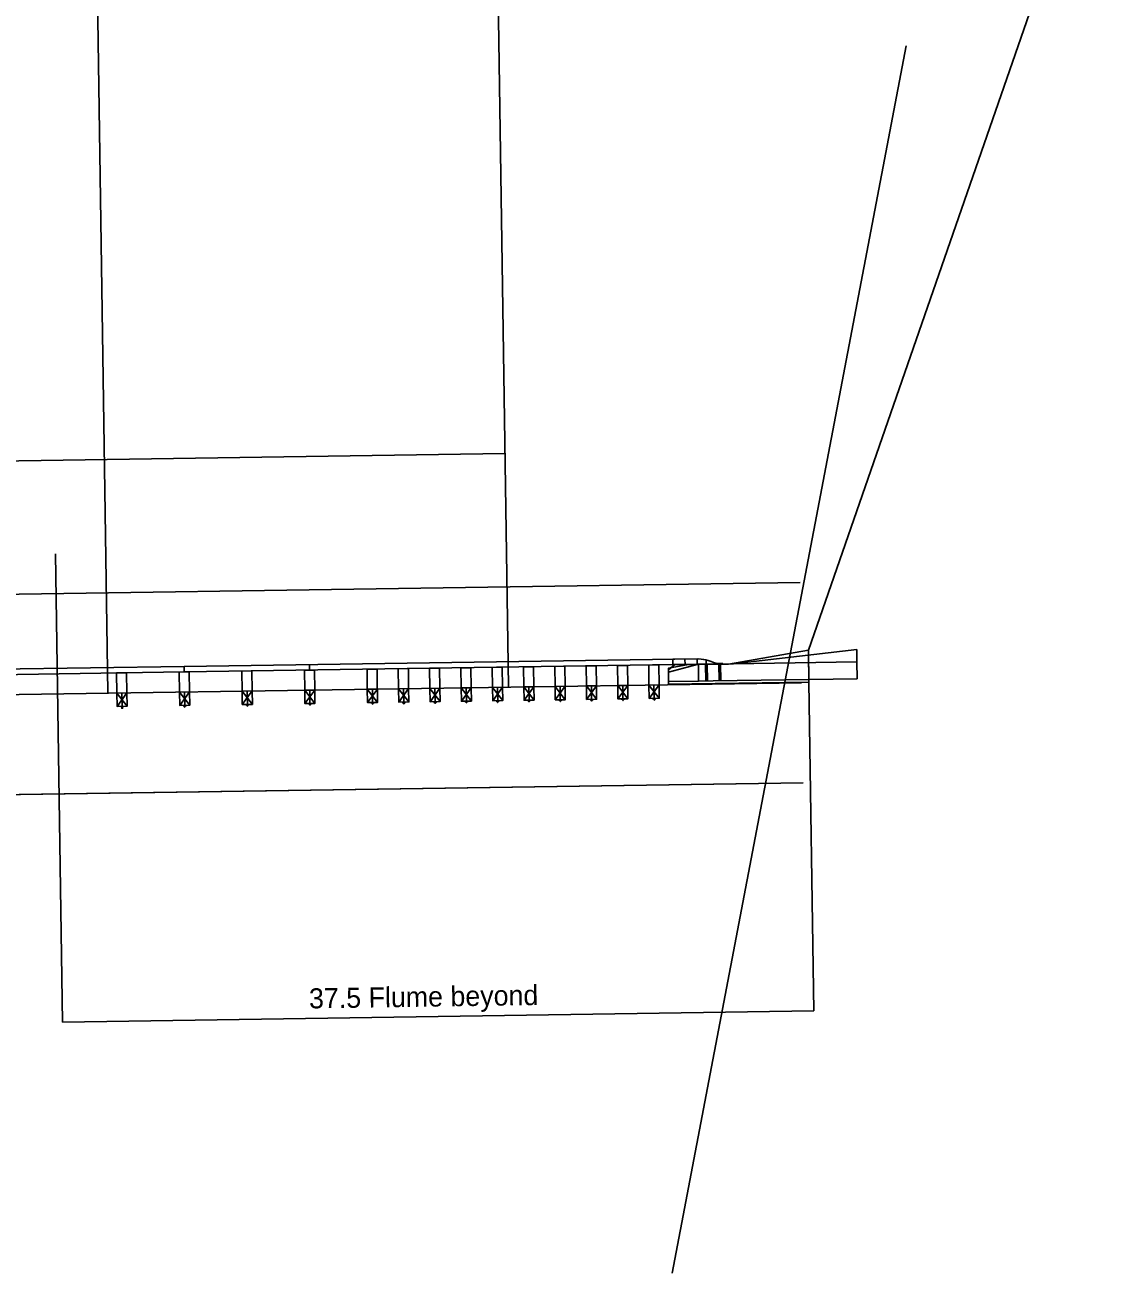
# Model space of a CAD drawing. Extents: x 17498307 to 17498862, y 7167523 to 7167641.
# Drawn here: x 17498437.4 to 17498491.8, y 7167527.9 to 7167590.2 of the extents above; entities that cross this region are included whole.
import ezdxf

# ---------------------------------------------------------------- set-up
doc = ezdxf.new("R2010")
doc.units = 0
for name, color, linetype in [('_CIVIL_CONSTRUCTION', 7, 'Continuous'), ('BridgeSuperStructure', 7, 'Continuous'), ('Default', 7, 'Continuous'), ('Draft_DNC', 7, 'Continuous'), ('dsnCellElements', 7, 'Continuous'), ('TL_ForeSlopeBarnRoof', 7, 'Continuous')]:
    doc.layers.add(name, color=color, linetype=linetype)

msp = doc.modelspace()

# ---------------------------------------------------------------- linework, layer by layer
at = {"layer": '_CIVIL_CONSTRUCTION'}
for p, q in [((17498441.492, 7167556.886), (17498440.787, 7167604.094)), ((17498461.49, 7167557.184), (17498460.785, 7167604.401)), ((17498491.825, 7167603.225), (17498476.465, 7167558.992)), ((17498411.322, 7167568.067), (17498461.316, 7167568.813)), ((17498404.41, 7167561.3), (17498476.05, 7167562.369)), ((17498404.484, 7167556.301), (17498476.124, 7167557.37))]:
    msp.add_line(p, q, dxfattribs=at)
at = {"layer": 'BridgeSuperStructure'}
msp.add_line((17498478.881, 7167559.027), (17498478.881, 7167559.027), dxfattribs=at)
at = {"layer": 'Default'}
msp.add_line((17498469.663, 7167527.904), (17498481.356, 7167589.172), dxfattribs=at)
msp.add_lwpolyline([(17498476.465, 7167558.991), (17498476.488, 7167557.408), (17498469.489, 7167557.304), (17498469.477, 7167558.095), (17498470.475, 7167558.277), (17498472.474, 7167558.306)], close=True, dxfattribs=at)
at = {"layer": 'Draft_DNC'}
for p, q in [((17498439.241, 7167540.434), (17498438.892, 7167563.803)), ((17498476.488, 7167557.408), (17498476.733, 7167540.993)), ((17498404.559, 7167551.301), (17498476.199, 7167552.37)), ((17498476.733, 7167540.993), (17498439.241, 7167540.434))]:
    msp.add_line(p, q, dxfattribs=at)
at = {"layer": 'dsnCellElements'}
for p, q in [((17498470.908, 7167558.565), (17498445.307, 7167558.182)), ((17498471.004, 7167558.566), (17498469.7, 7167558.546)), ((17498470.908, 7167558.565), (17498470.912, 7167558.294)), ((17498472.724, 7167558.321), (17498478.881, 7167559.027)), ((17498476.468, 7167558.75), (17498476.486, 7167557.533)), ((17498478.89, 7167558.413), (17498478.881, 7167559.027)), ((17498445.307, 7167558.182), (17498432.808, 7167557.995)), ((17498445.307, 7167558.182), (17498445.311, 7167557.911)), ((17498470.912, 7167558.294), (17498445.311, 7167557.911)), ((17498448.185, 7167557.952), (17498448.685, 7167557.96)), ((17498448.2, 7167556.953), (17498448.185, 7167557.952)), ((17498448.685, 7167557.96), (17498448.7, 7167556.961)), ((17498451.31, 7167557.999), (17498451.81, 7167558.007)), ((17498451.325, 7167557), (17498451.31, 7167557.999)), ((17498451.556, 7167558.275), (17498451.56, 7167558.004)), ((17498451.81, 7167558.007), (17498451.825, 7167557.007)), ((17498454.435, 7167558.046), (17498454.934, 7167558.053)), ((17498454.45, 7167557.046), (17498454.435, 7167558.046)), ((17498454.934, 7167558.053), (17498454.949, 7167557.054)), ((17498455.997, 7167558.069), (17498456.497, 7167558.077)), ((17498456.012, 7167557.07), (17498455.997, 7167558.069)), ((17498456.497, 7167558.077), (17498456.512, 7167557.077)), ((17498457.559, 7167558.092), (17498458.059, 7167558.1)), ((17498457.559, 7167558.092), (17498458.059, 7167558.1)), ((17498457.574, 7167557.093), (17498457.559, 7167558.092)), ((17498457.574, 7167557.093), (17498457.559, 7167558.092)), ((17498458.059, 7167558.1), (17498458.074, 7167557.1)), ((17498458.059, 7167558.1), (17498458.074, 7167557.1)), ((17498459.122, 7167558.116), (17498459.621, 7167558.123)), ((17498459.137, 7167557.116), (17498459.122, 7167558.116)), ((17498459.621, 7167558.123), (17498459.636, 7167557.124)), ((17498460.684, 7167558.139), (17498461.184, 7167558.146)), ((17498460.699, 7167557.14), (17498460.684, 7167558.139)), ((17498461.184, 7167558.146), (17498461.199, 7167557.147)), ((17498462.246, 7167558.162), (17498462.746, 7167558.17)), ((17498462.261, 7167557.163), (17498462.246, 7167558.162)), ((17498462.746, 7167558.17), (17498462.761, 7167557.17)), ((17498463.809, 7167558.186), (17498464.308, 7167558.193)), ((17498463.823, 7167557.186), (17498463.809, 7167558.186)), ((17498464.308, 7167558.193), (17498464.323, 7167557.194)), ((17498465.371, 7167558.209), (17498465.871, 7167558.216)), ((17498465.386, 7167557.21), (17498465.371, 7167558.209)), ((17498465.871, 7167558.216), (17498465.886, 7167557.217)), ((17498466.933, 7167558.232), (17498467.433, 7167558.24)), ((17498466.948, 7167557.233), (17498466.933, 7167558.232)), ((17498467.433, 7167558.24), (17498467.448, 7167557.24)), ((17498468.496, 7167558.256), (17498468.995, 7167558.263)), ((17498468.51, 7167557.256), (17498468.496, 7167558.256)), ((17498468.995, 7167558.263), (17498469.01, 7167557.264)), ((17498469.478, 7167558.022), (17498469.808, 7167558.277)), ((17498469.487, 7167557.428), (17498469.478, 7167558.022)), ((17498469.48, 7167557.897), (17498470.974, 7167558.295)), ((17498469.7, 7167558.546), (17498469.704, 7167558.276)), ((17498472.203, 7167558.313), (17498469.704, 7167558.276)), ((17498470.707, 7167558.291), (17498469.704, 7167558.276)), ((17498469.808, 7167558.277), (17498470.974, 7167558.295)), ((17498470.304, 7167558.555), (17498470.308, 7167558.285)), ((17498470.974, 7167558.295), (17498471.703, 7167558.306)), ((17498470.987, 7167557.451), (17498470.974, 7167558.295)), ((17498471.341, 7167557.456), (17498471.329, 7167558.3)), ((17498471.382, 7167557.509), (17498471.367, 7167558.511)), ((17498471.412, 7167558.301), (17498471.424, 7167557.457)), ((17498471.467, 7167558.48), (17498471.611, 7167558.426)), ((17498471.703, 7167558.306), (17498478.89, 7167558.413)), ((17498471.953, 7167558.335), (17498472.203, 7167558.339)), ((17498471.995, 7167558.31), (17498472.008, 7167557.466)), ((17498472.049, 7167557.519), (17498472.036, 7167558.337)), ((17498472.091, 7167557.467), (17498472.078, 7167558.311)), ((17498472.203, 7167558.313), (17498472.203, 7167558.339)), ((17498478.89, 7167558.413), (17498478.903, 7167557.569)), ((17498445.311, 7167557.911), (17498432.812, 7167557.725)), ((17498441.936, 7167557.861), (17498442.436, 7167557.868)), ((17498441.951, 7167556.86), (17498441.936, 7167557.861)), ((17498442.436, 7167557.868), (17498442.451, 7167556.867)), ((17498445.061, 7167557.906), (17498445.56, 7167557.913)), ((17498445.076, 7167556.906), (17498445.061, 7167557.906)), ((17498445.56, 7167557.913), (17498445.575, 7167556.914)), ((17498469.487, 7167557.428), (17498470.987, 7167557.451)), ((17498470.987, 7167557.451), (17498471.716, 7167557.462)), ((17498471.716, 7167557.462), (17498478.903, 7167557.569)), ((17498442.451, 7167556.867), (17498441.951, 7167556.86)), ((17498442.461, 7167556.201), (17498441.951, 7167556.86)), ((17498441.961, 7167556.193), (17498442.451, 7167556.867)), ((17498442.201, 7167556.864), (17498442.211, 7167556.197)), ((17498445.575, 7167556.914), (17498445.076, 7167556.906)), ((17498445.076, 7167556.906), (17498445.586, 7167556.247)), ((17498445.576, 7167556.914), (17498445.086, 7167556.24)), ((17498445.326, 7167556.91), (17498445.336, 7167556.244)), ((17498448.7, 7167556.961), (17498448.2, 7167556.953)), ((17498448.2, 7167556.953), (17498448.71, 7167556.294)), ((17498448.7, 7167556.961), (17498448.21, 7167556.287)), ((17498448.45, 7167556.957), (17498448.46, 7167556.29)), ((17498451.825, 7167557.007), (17498451.325, 7167557)), ((17498451.325, 7167557), (17498451.835, 7167556.341)), ((17498451.825, 7167557.007), (17498451.335, 7167556.333)), ((17498451.575, 7167557.003), (17498451.585, 7167556.337)), ((17498454.949, 7167557.054), (17498454.45, 7167557.046)), ((17498454.45, 7167557.046), (17498454.959, 7167556.387)), ((17498454.95, 7167557.054), (17498454.46, 7167556.38)), ((17498454.7, 7167557.05), (17498454.709, 7167556.384)), ((17498456.512, 7167557.077), (17498456.012, 7167557.07)), ((17498456.012, 7167557.07), (17498456.522, 7167556.411)), ((17498456.512, 7167557.077), (17498456.022, 7167556.403)), ((17498456.262, 7167557.073), (17498456.272, 7167556.407)), ((17498458.074, 7167557.1), (17498457.574, 7167557.093)), ((17498458.074, 7167557.1), (17498457.574, 7167557.093)), ((17498457.574, 7167557.093), (17498458.084, 7167556.434)), ((17498458.074, 7167557.1), (17498457.584, 7167556.426)), ((17498457.824, 7167557.097), (17498457.834, 7167556.43)), ((17498459.636, 7167557.124), (17498459.137, 7167557.116)), ((17498459.137, 7167557.116), (17498459.646, 7167556.457)), ((17498459.636, 7167557.124), (17498459.146, 7167556.45)), ((17498459.387, 7167557.12), (17498459.396, 7167556.454)), ((17498461.199, 7167557.147), (17498460.699, 7167557.14)), ((17498460.699, 7167557.14), (17498461.209, 7167556.481)), ((17498461.199, 7167557.147), (17498460.709, 7167556.473)), ((17498460.949, 7167557.143), (17498460.959, 7167556.477)), ((17498462.761, 7167557.17), (17498462.261, 7167557.163)), ((17498462.261, 7167557.163), (17498462.771, 7167556.504)), ((17498462.761, 7167557.17), (17498462.271, 7167556.496)), ((17498462.511, 7167557.167), (17498462.521, 7167556.5)), ((17498464.323, 7167557.194), (17498463.823, 7167557.186)), ((17498463.823, 7167557.186), (17498464.333, 7167556.527)), ((17498464.323, 7167557.194), (17498463.833, 7167556.52)), ((17498464.073, 7167557.19), (17498464.083, 7167556.523)), ((17498465.886, 7167557.217), (17498465.386, 7167557.21)), ((17498465.386, 7167557.21), (17498465.896, 7167556.551)), ((17498465.886, 7167557.217), (17498465.396, 7167556.543)), ((17498465.636, 7167557.213), (17498465.646, 7167556.547)), ((17498467.448, 7167557.24), (17498466.948, 7167557.233)), ((17498466.948, 7167557.233), (17498467.458, 7167556.574)), ((17498467.448, 7167557.24), (17498466.958, 7167556.566)), ((17498467.198, 7167557.237), (17498467.208, 7167556.57)), ((17498469.01, 7167557.264), (17498468.51, 7167557.256)), ((17498468.51, 7167557.256), (17498469.02, 7167556.597)), ((17498469.01, 7167557.264), (17498468.52, 7167556.59)), ((17498468.76, 7167557.26), (17498468.77, 7167556.593)), ((17498442.212, 7167556.1), (17498442.212, 7167556.093)), ((17498445.086, 7167556.24), (17498445.586, 7167556.247)), ((17498445.256, 7167556.242), (17498445.256, 7167556.226)), ((17498445.256, 7167556.226), (17498445.416, 7167556.228)), ((17498445.296, 7167556.226), (17498445.296, 7167556.189)), ((17498445.296, 7167556.189), (17498445.376, 7167556.19)), ((17498445.312, 7167556.227), (17498445.312, 7167556.189)), ((17498445.326, 7167556.19), (17498445.327, 7167556.16)), ((17498445.327, 7167556.16), (17498445.347, 7167556.16)), ((17498445.346, 7167556.19), (17498445.347, 7167556.16)), ((17498445.36, 7167556.227), (17498445.36, 7167556.19)), ((17498445.376, 7167556.228), (17498445.376, 7167556.19)), ((17498445.416, 7167556.245), (17498445.416, 7167556.228)), ((17498448.21, 7167556.287), (17498448.71, 7167556.294)), ((17498448.38, 7167556.289), (17498448.38, 7167556.273)), ((17498448.38, 7167556.273), (17498448.54, 7167556.275)), ((17498448.42, 7167556.273), (17498448.421, 7167556.236)), ((17498448.421, 7167556.236), (17498448.501, 7167556.237)), ((17498448.436, 7167556.273), (17498448.437, 7167556.236)), ((17498448.451, 7167556.236), (17498448.451, 7167556.207)), ((17498448.451, 7167556.207), (17498448.471, 7167556.207)), ((17498448.471, 7167556.236), (17498448.471, 7167556.207)), ((17498448.484, 7167556.274), (17498448.485, 7167556.237)), ((17498448.5, 7167556.274), (17498448.501, 7167556.237)), ((17498448.54, 7167556.291), (17498448.54, 7167556.275)), ((17498451.335, 7167556.333), (17498451.835, 7167556.341)), ((17498451.505, 7167556.336), (17498451.505, 7167556.319)), ((17498451.505, 7167556.319), (17498451.665, 7167556.322)), ((17498451.545, 7167556.32), (17498451.546, 7167556.282)), ((17498451.546, 7167556.282), (17498451.626, 7167556.284)), ((17498451.561, 7167556.32), (17498451.562, 7167556.283)), ((17498451.576, 7167556.283), (17498451.576, 7167556.253)), ((17498451.576, 7167556.253), (17498451.596, 7167556.254)), ((17498451.596, 7167556.283), (17498451.596, 7167556.254)), ((17498451.609, 7167556.321), (17498451.61, 7167556.283)), ((17498451.625, 7167556.321), (17498451.626, 7167556.284)), ((17498451.665, 7167556.338), (17498451.665, 7167556.322)), ((17498454.46, 7167556.38), (17498454.959, 7167556.387)), ((17498454.629, 7167556.382), (17498454.63, 7167556.366)), ((17498454.63, 7167556.366), (17498454.79, 7167556.368)), ((17498454.67, 7167556.366), (17498454.67, 7167556.329)), ((17498454.67, 7167556.329), (17498454.75, 7167556.33)), ((17498454.686, 7167556.367), (17498454.686, 7167556.329)), ((17498454.7, 7167556.329), (17498454.701, 7167556.3)), ((17498454.701, 7167556.3), (17498454.721, 7167556.3)), ((17498454.72, 7167556.33), (17498454.721, 7167556.3)), ((17498454.734, 7167556.367), (17498454.734, 7167556.33)), ((17498454.75, 7167556.368), (17498454.75, 7167556.33)), ((17498454.789, 7167556.385), (17498454.79, 7167556.368)), ((17498456.022, 7167556.403), (17498456.522, 7167556.411)), ((17498456.192, 7167556.406), (17498456.192, 7167556.389)), ((17498456.192, 7167556.389), (17498456.352, 7167556.392)), ((17498456.232, 7167556.39), (17498456.233, 7167556.352)), ((17498456.233, 7167556.352), (17498456.313, 7167556.354)), ((17498456.248, 7167556.39), (17498456.249, 7167556.353)), ((17498456.263, 7167556.353), (17498456.263, 7167556.323)), ((17498456.263, 7167556.323), (17498456.283, 7167556.324)), ((17498456.283, 7167556.353), (17498456.283, 7167556.324)), ((17498456.296, 7167556.391), (17498456.297, 7167556.353)), ((17498456.312, 7167556.391), (17498456.313, 7167556.354)), ((17498456.352, 7167556.408), (17498456.352, 7167556.392)), ((17498457.584, 7167556.426), (17498458.084, 7167556.434)), ((17498457.754, 7167556.429), (17498457.754, 7167556.412)), ((17498457.754, 7167556.412), (17498457.914, 7167556.415)), ((17498457.794, 7167556.413), (17498457.795, 7167556.376)), ((17498457.795, 7167556.376), (17498457.875, 7167556.377)), ((17498457.81, 7167556.413), (17498457.811, 7167556.376)), ((17498457.825, 7167556.376), (17498457.825, 7167556.347)), ((17498457.825, 7167556.347), (17498457.845, 7167556.347)), ((17498457.845, 7167556.376), (17498457.845, 7167556.347)), ((17498457.858, 7167556.414), (17498457.859, 7167556.377)), ((17498457.874, 7167556.414), (17498457.875, 7167556.377)), ((17498457.914, 7167556.431), (17498457.914, 7167556.415)), ((17498459.146, 7167556.45), (17498459.646, 7167556.457)), ((17498459.316, 7167556.452), (17498459.317, 7167556.436)), ((17498459.317, 7167556.436), (17498459.477, 7167556.438)), ((17498459.357, 7167556.436), (17498459.357, 7167556.399)), ((17498459.357, 7167556.399), (17498459.437, 7167556.4)), ((17498459.373, 7167556.437), (17498459.373, 7167556.399)), ((17498459.387, 7167556.399), (17498459.388, 7167556.37)), ((17498459.388, 7167556.37), (17498459.408, 7167556.37)), ((17498459.407, 7167556.4), (17498459.408, 7167556.37)), ((17498459.421, 7167556.437), (17498459.421, 7167556.4)), ((17498459.437, 7167556.438), (17498459.437, 7167556.4)), ((17498459.476, 7167556.455), (17498459.477, 7167556.438)), ((17498460.709, 7167556.473), (17498461.209, 7167556.481)), ((17498460.879, 7167556.476), (17498460.879, 7167556.459)), ((17498460.879, 7167556.459), (17498461.039, 7167556.461)), ((17498460.919, 7167556.46), (17498460.92, 7167556.422)), ((17498460.92, 7167556.422), (17498461, 7167556.423)), ((17498460.935, 7167556.46), (17498460.936, 7167556.423)), ((17498460.95, 7167556.423), (17498460.95, 7167556.393)), ((17498460.95, 7167556.393), (17498460.97, 7167556.394)), ((17498460.97, 7167556.423), (17498460.97, 7167556.394)), ((17498460.983, 7167556.461), (17498460.984, 7167556.423)), ((17498460.999, 7167556.461), (17498461, 7167556.423)), ((17498461.039, 7167556.478), (17498461.039, 7167556.461)), ((17498462.271, 7167556.496), (17498462.771, 7167556.504)), ((17498462.441, 7167556.499), (17498462.441, 7167556.482)), ((17498462.441, 7167556.482), (17498462.601, 7167556.485)), ((17498462.481, 7167556.483), (17498462.482, 7167556.446)), ((17498462.482, 7167556.446), (17498462.562, 7167556.447)), ((17498462.497, 7167556.483), (17498462.498, 7167556.446)), ((17498462.512, 7167556.446), (17498462.512, 7167556.417)), ((17498462.512, 7167556.417), (17498462.532, 7167556.417)), ((17498462.532, 7167556.446), (17498462.532, 7167556.417)), ((17498462.545, 7167556.484), (17498462.546, 7167556.447)), ((17498462.561, 7167556.484), (17498462.562, 7167556.447)), ((17498462.601, 7167556.501), (17498462.601, 7167556.485)), ((17498463.833, 7167556.52), (17498464.333, 7167556.527)), ((17498464.003, 7167556.522), (17498464.004, 7167556.506)), ((17498464.004, 7167556.506), (17498464.164, 7167556.508)), ((17498464.044, 7167556.506), (17498464.044, 7167556.469)), ((17498464.044, 7167556.469), (17498464.124, 7167556.47)), ((17498464.06, 7167556.507), (17498464.06, 7167556.469)), ((17498464.074, 7167556.469), (17498464.075, 7167556.44)), ((17498464.075, 7167556.44), (17498464.095, 7167556.44)), ((17498464.094, 7167556.47), (17498464.095, 7167556.44)), ((17498464.108, 7167556.507), (17498464.108, 7167556.47)), ((17498464.124, 7167556.508), (17498464.124, 7167556.47)), ((17498464.163, 7167556.525), (17498464.164, 7167556.508)), ((17498465.396, 7167556.543), (17498465.896, 7167556.551)), ((17498465.566, 7167556.546), (17498465.566, 7167556.529)), ((17498465.566, 7167556.529), (17498465.726, 7167556.531)), ((17498465.606, 7167556.53), (17498465.607, 7167556.492)), ((17498465.607, 7167556.492), (17498465.687, 7167556.493)), ((17498465.622, 7167556.53), (17498465.623, 7167556.493)), ((17498465.637, 7167556.493), (17498465.637, 7167556.463)), ((17498465.637, 7167556.463), (17498465.657, 7167556.464)), ((17498465.657, 7167556.493), (17498465.657, 7167556.464)), ((17498465.67, 7167556.531), (17498465.671, 7167556.493)), ((17498465.686, 7167556.531), (17498465.687, 7167556.493)), ((17498465.726, 7167556.548), (17498465.726, 7167556.531)), ((17498466.958, 7167556.566), (17498467.458, 7167556.574)), ((17498467.128, 7167556.569), (17498467.128, 7167556.552)), ((17498467.128, 7167556.552), (17498467.288, 7167556.555)), ((17498467.168, 7167556.553), (17498467.169, 7167556.516)), ((17498467.169, 7167556.516), (17498467.249, 7167556.517)), ((17498467.184, 7167556.553), (17498467.185, 7167556.516)), ((17498467.199, 7167556.516), (17498467.199, 7167556.487)), ((17498467.199, 7167556.487), (17498467.219, 7167556.487)), ((17498467.219, 7167556.516), (17498467.219, 7167556.487)), ((17498467.232, 7167556.554), (17498467.233, 7167556.517)), ((17498467.248, 7167556.554), (17498467.249, 7167556.517)), ((17498467.288, 7167556.571), (17498467.288, 7167556.555)), ((17498468.52, 7167556.59), (17498469.02, 7167556.597)), ((17498468.69, 7167556.592), (17498468.691, 7167556.576)), ((17498468.691, 7167556.576), (17498468.851, 7167556.578)), ((17498468.731, 7167556.576), (17498468.731, 7167556.539)), ((17498468.731, 7167556.539), (17498468.811, 7167556.54)), ((17498468.747, 7167556.577), (17498468.747, 7167556.539)), ((17498468.761, 7167556.539), (17498468.762, 7167556.51)), ((17498468.762, 7167556.51), (17498468.782, 7167556.51)), ((17498468.781, 7167556.54), (17498468.782, 7167556.51)), ((17498468.795, 7167556.577), (17498468.795, 7167556.54)), ((17498468.811, 7167556.577), (17498468.811, 7167556.54)), ((17498468.85, 7167556.595), (17498468.851, 7167556.578))]:
    msp.add_line(p, q, dxfattribs=at)
for points in [[(17498442.451, 7167556.867), (17498441.951, 7167556.86), (17498441.961, 7167556.193), (17498442.461, 7167556.201)], [(17498445.576, 7167556.914), (17498445.076, 7167556.906), (17498445.086, 7167556.24), (17498445.586, 7167556.247)], [(17498448.7, 7167556.961), (17498448.2, 7167556.953), (17498448.21, 7167556.287), (17498448.71, 7167556.294)], [(17498451.825, 7167557.007), (17498451.325, 7167557), (17498451.335, 7167556.333), (17498451.835, 7167556.341)], [(17498454.95, 7167557.054), (17498454.45, 7167557.046), (17498454.46, 7167556.38), (17498454.959, 7167556.387)], [(17498456.512, 7167557.077), (17498456.012, 7167557.07), (17498456.022, 7167556.403), (17498456.522, 7167556.411)], [(17498458.074, 7167557.1), (17498457.574, 7167557.093), (17498457.584, 7167556.426), (17498458.084, 7167556.434)], [(17498459.636, 7167557.124), (17498459.137, 7167557.116), (17498459.146, 7167556.45), (17498459.646, 7167556.457)], [(17498461.199, 7167557.147), (17498460.699, 7167557.14), (17498460.709, 7167556.473), (17498461.209, 7167556.481)], [(17498462.761, 7167557.17), (17498462.261, 7167557.163), (17498462.271, 7167556.496), (17498462.771, 7167556.504)], [(17498464.323, 7167557.194), (17498463.823, 7167557.186), (17498463.833, 7167556.52), (17498464.333, 7167556.527)], [(17498465.886, 7167557.217), (17498465.386, 7167557.21), (17498465.396, 7167556.543), (17498465.896, 7167556.551)], [(17498467.448, 7167557.24), (17498466.948, 7167557.233), (17498466.958, 7167556.566), (17498467.458, 7167556.574)], [(17498469.01, 7167557.264), (17498468.51, 7167557.256), (17498468.52, 7167556.59), (17498469.02, 7167556.597)]]:
    msp.add_lwpolyline(points, close=True, dxfattribs=at)
for points in [[(17498442.244, 7167556.198), (17498442.245, 7167556.155), (17498442.178, 7167556.154), (17498442.178, 7167556.197)], [(17498442.231, 7167556.154), (17498442.232, 7167556.1), (17498442.193, 7167556.1), (17498442.192, 7167556.154)]]:
    msp.add_lwpolyline(points, dxfattribs=at)
for centre, major_axis, start_param, end_param in [((17498470.947, 7167557.07), (-1.541, -0.023), 4.353641, 4.661204), ((17498472.145, 7167559.661), (1.379, 0.021), 4.300427, 4.558114)]:
    msp.add_ellipse(centre, major_axis=major_axis, ratio=0.97085, start_param=start_param, end_param=end_param, dxfattribs=at)
at = {"layer": 'TL_ForeSlopeBarnRoof'}
msp.add_lwpolyline([(17498337.156, 7167548.396), (17498357.092, 7167548.701), (17498380.925, 7167550.005), (17498404.759, 7167551.308), (17498476.199, 7167552.37)], dxfattribs=at)

# ---------------------------------------------------------------- texts
at = {"layer": 'Draft_DNC'}
msp.add_text('37.5 Flume beyond', height=1, rotation=0.85524, dxfattribs=at).set_placement((17498451.545, 7167541.113))

doc.saveas('drawing.dxf')
